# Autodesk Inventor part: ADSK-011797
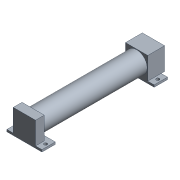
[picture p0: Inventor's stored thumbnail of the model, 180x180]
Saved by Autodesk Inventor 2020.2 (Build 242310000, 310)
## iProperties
Created: 2000-01
Part Number: ADSK-011797
Material: Pearson Aluminium
Document SubType Name: Modeling
Designer: cmcgourin
Density: 2.71 g/cm^3
Appearance: Pearson-Aluminum
Mass: 3170.46 g
Surface Area: 988.242 cm^2
Volume: 1169.91 cm^3
Control State: 0
Checked Out: False
Master: False
Shininess: 35.0
Length Units: 11269
Angle Units: 11279
Time Units: 11290
Mass Units: 11283
Length Display Precision: 3
Angle Display Precision: 2
Compacted: True
Dimensions: 69,5x374x100 mm
Mass: 3,17 kg
DocNumber: ADSK-011797.ipt
Folder: 01 - Themengebiete\Simplification\01 - Packaging machine\
VDS_Category: 3D Komponenten
VLT_Material: Pearson Aluminium
Density: 2.71
Volumn: 1184.4338293599712
Area: 988.1236565926313
PropertySet Name: Model Information
Author: cmcgourin
Revision Number: -
Title: cylinder
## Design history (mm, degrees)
node "Solide1"
  node "Extrusion1" dims "d2" = 10, "d3" = 0
  node "Extrusion2" dims "d4" = 38, "d5" = 0
  node "Extrusion3" dims "d7" = 295, "d8" = 0
  node "Extrusion4" dims "d9" = 25, "d10" = 0
  node "Extrusion5" dims "d17" = 6, "d18" = 0
  node "Extrusion6" dims "d22" = 6, "d23" = 0
  node "Extrusion7" dims "d36" = 6, "d37" = 0
  node "Hole1" dims "d27" = 9, "d28" = 9.525, "d29" = 6.35, "d30" = 60 deg, "d31" = 19.05, "d32" = 118 deg, "d57" = 6
  node "Hole2" dims "d41" = 9, "d42" = 9.525, "d43" = 6.35, "d44" = 60 deg, "d45" = 19.05, "d46" = 118 deg, "d58" = 6
  node "Hole3" dims "d50" = 10.106, "d51" = 9.525, "d52" = 6.35, "d53" = 60 deg, "d54" = 32.3, "d55" = 0, "d59" = 24
sketch "Sketch1"
  geometry: L1 (-31.75, -31.75)-(31.75, -31.75); L2 (31.75, -31.75)-(31.75, 31.75); L3 (31.75, 31.75)-(-31.75, 31.75); L4 (-31.75, 31.75)-(-31.75, -31.75); 3 further points
  constraints: 8 end point, 2 midpoint, 2 parallel, 1 horizontal, 1 horizontal alignment, 1 perpendicular, 1 vertical alignment
  dimensions: "d0" = 63.5 distance of L3.end L1.start; "d1" = 63.5 distance of L2.end L3.end
sketch "Sketch2"
  geometry: L1 (-31.75, -31.75)-(31.75, -31.75) reference; L2 (31.75, -31.75)-(31.75, 31.75) reference; L3 (31.75, 31.75)-(-31.75, 31.75) reference; L4 (-31.75, 31.75)-(-31.75, -31.75) reference
sketch "Sketch3"
  geometry: C1 r 30 at (0, 0); 1 further point
  constraints: 1 centre point, 1 coincident
  dimensions: "d6" = 60 diameter of C1
workplane "Arbeitsebene2"
sketch "Sketch6"
  geometry: L1 (-31.75, 31.75)-(31.75, 31.75) reference; L2 (0, 13.5)-(0, -13.5); L3 (-31.75, -31.75)-(-31.75, 31.75) reference; C1 r 11.5 at (0, 13.5); C2 r 11.5 at (0, -13.5); C3 r 8 at (0, 13.5); C4 r 8 at (0, -13.5); 3 further points
  constraints: 4 centre point, 3 midpoint, 2 end point, 1 horizontal alignment, 1 vertical, 1 vertical alignment
  dimensions: "d12" = 23 diameter of C2 (= d13); "d13" = 23 diameter of C1; "d15" = 16 diameter of C3; "d16" = 16 diameter of C4 (= d15); "d56" = 27 distance of L2.start L2.end
sketch "Sketch7"
  geometry: L1 (63.5, 48)-(0, 48) reference; L2 (-18.25, 48)-(81.75, 48); L3 (81.75, 48)-(81.75, 10); L4 (81.75, 10)-(-18.25, 10); L5 (-18.25, 10)-(-18.25, 48); L6 (0, 0)-(63.5, 0) reference; 2 further points
  constraints: 8 end point, 2 midpoint, 2 parallel, 1 collinear, 1 horizontal, 1 perpendicular, 1 vertical alignment
  dimensions: "d19" = 100 distance of L2.start L2.end; "d20" = 38 distance of L4.end L2.start
sketch "Sketch8"
  geometry: L1 (-18.25, 48)-(81.75, 48) reference; L2 (-9.5, 29)-(73, 29); L3 (101.75, 189)-(-38.25, 189) reference; 2 further points
  constraints: 2 end point, 2 midpoint, 1 horizontal, 1 horizontal alignment, 1 vertical alignment
  dimensions: "d25" = 82.5 distance of L2.end L2.start; "d62" = 160 distance from line of L3 L2.start
sketch "Sketch9"
  geometry: L1 (63.5, 25)-(0, 25) reference; L2 (-18.25, 25)-(81.75, 25); L3 (81.75, 25)-(81.75, -13); L4 (81.75, -13)-(-18.25, -13); L5 (-18.25, -13)-(-18.25, 25); 2 further points
  constraints: 8 end point, 3 midpoint, 2 parallel, 1 coincident, 1 collinear, 1 horizontal, 1 perpendicular
  dimensions: "d33" = 38 distance of L4.end L2.start; "d34" = 100 distance of L3.end L4.end
sketch "Sketch10"
  geometry: L1 (-18.25, 25)-(81.75, 25) reference; L2 (73, 6)-(-9.5, 6); L3 (101.75, -154)-(-38.25, -154) reference; 2 further points
  constraints: 2 end point, 2 midpoint, 1 horizontal, 1 horizontal alignment, 1 vertical alignment
  dimensions: "d39" = 82.5 distance of L2.start L2.end; "d63" = 160 distance from line of L3 L2.end
node "Corps solides"
node "Corps surfaciques"
sketch "Sketch5"
  geometry: L1 (31.75, -31.75)-(-31.75, -31.75) reference; L2 (-31.75, -31.75)-(-31.75, 31.75) reference; L3 (31.75, 31.75)-(31.75, -31.75) reference; L4 (-31.75, 31.75)-(31.75, 31.75) reference
sketch "Sketch11"
  geometry: L1 (0, 63.5)-(48, 63.5) reference; L2 (-304.8, 6.35)-(-304.8, 57.15) reference; 2 further points
  constraints: 1 horizontal alignment
  dimensions: "d47" = 339.725 distance from line of point (34.925, 31.75) L2; "d48" = 320.675 distance of point (355.6, 31.75) point (34.925, 31.75); "d49" = 31.75 distance from line of L1 point (34.925, 31.75)
